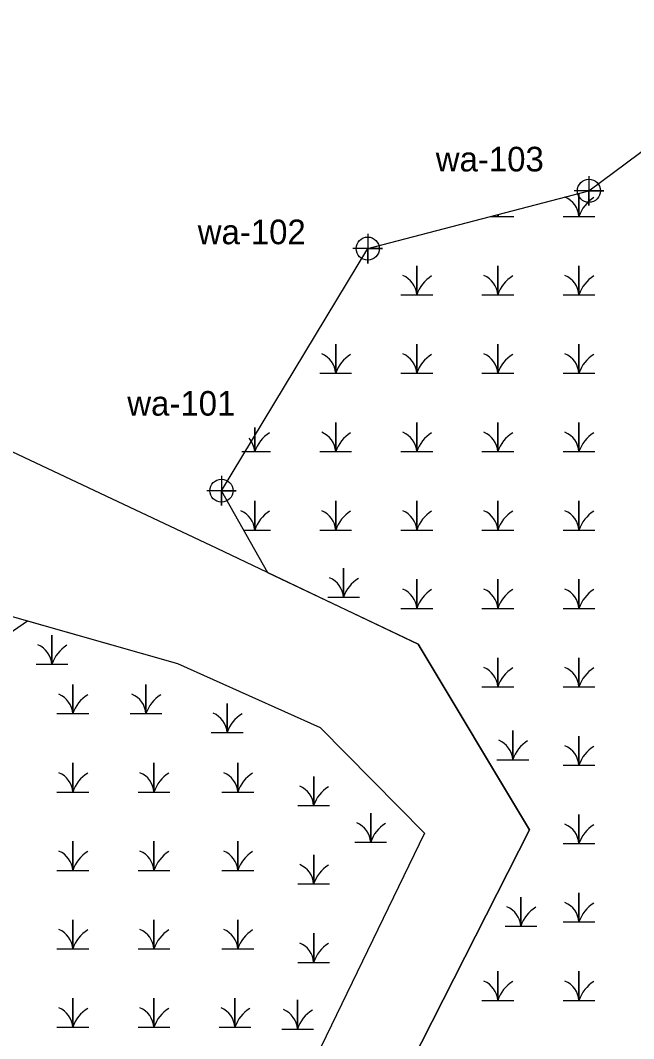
# Model space of a CAD drawing. Extents: x 2379288 to 2381905, y 330670 to 333511.
# Drawn here: x 2380359.8 to 2380484.3, y 332166.7 to 332373.5 of the extents above; entities that cross this region are included whole.
import ezdxf

# ---------------------------------------------------------------- set-up
doc = ezdxf.new("R2010")
doc.units = 0
for name, color, linetype in [('Exist Environmental Wetland Boundary', 7, 'Continuous'), ('Exist Environmental Wetland Boundary Cogo Number', 7, 'Continuous'), ('Exist Environmental Wetland Boundary Cogo Point CELL', 7, 'Continuous'), ('Exist Hydro Jurisdictional Stream or Body of Water Mitigable', 7, 'Continuous'), ('Exist Hydro Swamp or Marsh', 7, 'Continuous')]:
    doc.layers.add(name, color=color, linetype=linetype)

msp = doc.modelspace()

# ---------------------------------------------------------------- linework, layer by layer
at = {"layer": 'Exist Environmental Wetland Boundary'}
for points in [[(2380442.38, 332045.91), (2380445.79, 332068.31), (2380430.27, 332144.34), (2380463.17, 332209.13), (2380440.55, 332246.83), (2380410.07, 332261.34), (2380400.64, 332277.99), (2380430.32, 332327.14), (2380475.22, 332338.88), (2380523.99, 332375.18), (2380571.84, 332459.01), (2380602.28, 332487.78), (2380643.42, 332522.54), (2380698.01, 332520.45), (2380758.16, 332538.88), (2380814.95, 332532.8), (2380827.75, 332553.62), (2380815.96, 332612.38), (2380841.18, 332668.4), (2380857.01, 332670.65), (2380837.85, 332627.97), (2380932.82, 332657.69)], [(2380190.43, 331937.74), (2380215.91, 331979.8), (2380228.91, 332002.01), (2380260.36, 332058.66), (2380273.37, 332080.17), (2380301.41, 332125.81), (2380310.82, 332140.92), (2380328.42, 332178.94), (2380338.55, 332196.72), (2380340.11, 332203.44), (2380335.84, 332213), (2380327.12, 332226.26), (2380352.5, 332245.53), (2380361.25, 332251.56), (2380391.69, 332242.92), (2380420.68, 332229.92), (2380441.85, 332208.47), (2380413.47, 332149.9), (2380414.24, 332071.02), (2380410.1, 331991.07)]]:
    msp.add_lwpolyline(points, dxfattribs=at)
at = {"layer": 'Exist Environmental Wetland Boundary Cogo Point CELL'}
for points in [[(2380475.21, 332341.88), (2380475.21, 332335.88), (2380475.21, 332338.88), (2380478.21, 332338.88), (2380472.21, 332338.88)], [(2380430.32, 332330.14), (2380430.32, 332324.14), (2380430.32, 332327.14), (2380433.32, 332327.14), (2380427.32, 332327.14)], [(2380400.64, 332280.99), (2380400.64, 332274.99), (2380400.64, 332277.99), (2380403.64, 332277.99), (2380397.64, 332277.99)]]:
    msp.add_lwpolyline(points, dxfattribs=at)
for centre in [(2380475.21, 332338.88), (2380430.32, 332327.14), (2380400.64, 332277.99)]:
    msp.add_circle(centre, 2.34, dxfattribs=at)
at = {"layer": 'Exist Hydro Jurisdictional Stream or Body of Water Mitigable'}
for points in [[(2380185.2, 332357.15), (2380244.82, 332322.56), (2380311.82, 332307.72), (2380399.67, 332266.29), (2380440.55, 332246.83), (2380463.17, 332209.13), (2380430.27, 332144.34), (2380445.79, 332068.31), (2380442.38, 332045.91)], [(2380184.84, 332330.77), (2380227.89, 332300.41), (2380296.91, 332269.82), (2380391.69, 332242.92), (2380420.68, 332229.92), (2380441.85, 332208.47), (2380413.47, 332149.9), (2380414.24, 332071.02), (2380410.1, 331991.07)]]:
    msp.add_lwpolyline(points, dxfattribs=at)
at = {"layer": 'Exist Hydro Swamp or Marsh'}
for points in [[(2380469.96, 332333.67), (2380473.19, 332333.67), (2380473.19, 332338.35)], [(2380473.19, 332338.35), (2380473.19, 332333.67), (2380476.42, 332333.67)], [(2380455.29, 332333.67), (2380456.74, 332333.67), (2380456.74, 332334.05)], [(2380456.74, 332334.05), (2380456.74, 332333.67), (2380459.96, 332333.67)], [(2380437.06, 332317.75), (2380440.29, 332317.75), (2380440.29, 332323.67), (2380440.29, 332317.75), (2380443.51, 332317.75)], [(2380453.51, 332317.75), (2380456.74, 332317.75), (2380456.74, 332323.67), (2380456.74, 332317.75), (2380459.96, 332317.75)], [(2380469.96, 332317.75), (2380473.19, 332317.75), (2380473.19, 332323.67), (2380473.19, 332317.75), (2380476.42, 332317.75)], [(2380420.61, 332301.83), (2380423.84, 332301.83), (2380423.84, 332307.75), (2380423.84, 332301.83), (2380427.06, 332301.83)], [(2380437.06, 332301.83), (2380440.29, 332301.83), (2380440.29, 332307.75), (2380440.29, 332301.83), (2380443.51, 332301.83)], [(2380453.51, 332301.83), (2380456.74, 332301.83), (2380456.74, 332307.75), (2380456.74, 332301.83), (2380459.96, 332301.83)], [(2380469.96, 332301.83), (2380473.19, 332301.83), (2380473.19, 332307.75), (2380473.19, 332301.83), (2380476.42, 332301.83)], [(2380420.61, 332285.91), (2380423.84, 332285.91), (2380423.84, 332291.83), (2380423.84, 332285.91), (2380427.06, 332285.91)], [(2380437.06, 332285.91), (2380440.29, 332285.91), (2380440.29, 332291.83), (2380440.29, 332285.91), (2380443.51, 332285.91)], [(2380453.51, 332285.91), (2380456.74, 332285.91), (2380456.74, 332291.83), (2380456.74, 332285.91), (2380459.96, 332285.91)], [(2380469.96, 332285.91), (2380473.19, 332285.91), (2380473.19, 332291.83), (2380473.19, 332285.91), (2380476.42, 332285.91)], [(2380404.8, 332285.91), (2380407.38, 332285.91), (2380407.38, 332290.84)], [(2380407.38, 332290.84), (2380407.38, 332285.91), (2380410.61, 332285.91)], [(2380405.17, 332270), (2380407.38, 332270), (2380407.38, 332275.91), (2380407.38, 332270), (2380410.61, 332270)], [(2380420.61, 332270), (2380423.84, 332270), (2380423.84, 332275.91), (2380423.84, 332270), (2380427.06, 332270)], [(2380437.06, 332270), (2380440.29, 332270), (2380440.29, 332275.91), (2380440.29, 332270), (2380443.51, 332270)], [(2380453.51, 332270), (2380456.74, 332270), (2380456.74, 332275.91), (2380456.74, 332270), (2380459.96, 332270)], [(2380469.96, 332270), (2380473.19, 332270), (2380473.19, 332275.91), (2380473.19, 332270), (2380476.42, 332270)], [(2380422.2, 332256.35), (2380425.42, 332256.35), (2380425.42, 332262.27), (2380425.42, 332256.35), (2380428.65, 332256.35)], [(2380437.06, 332254.08), (2380440.29, 332254.08), (2380440.29, 332260), (2380440.29, 332254.08), (2380443.51, 332254.08)], [(2380453.51, 332254.08), (2380456.74, 332254.08), (2380456.74, 332260), (2380456.74, 332254.08), (2380459.96, 332254.08)], [(2380469.96, 332254.08), (2380473.19, 332254.08), (2380473.19, 332260), (2380473.19, 332254.08), (2380476.42, 332254.08)], [(2380363, 332242.75), (2380366.22, 332242.75), (2380366.22, 332248.67), (2380366.22, 332242.75), (2380369.45, 332242.75)], [(2380453.51, 332238.16), (2380456.74, 332238.16), (2380456.74, 332244.08), (2380456.74, 332238.16), (2380459.96, 332238.16)], [(2380469.96, 332238.16), (2380473.19, 332238.16), (2380473.19, 332244.08), (2380473.19, 332238.16), (2380476.42, 332238.16)], [(2380367.25, 332232.72), (2380370.48, 332232.72), (2380370.48, 332238.64), (2380370.48, 332232.72), (2380373.7, 332232.72)], [(2380382.09, 332232.72), (2380385.31, 332232.72), (2380385.31, 332238.64), (2380385.31, 332232.72), (2380388.54, 332232.72)], [(2380398.57, 332228.87), (2380401.8, 332228.87), (2380401.8, 332234.79), (2380401.8, 332228.87), (2380405.02, 332228.87)], [(2380456.54, 332223.37), (2380459.77, 332223.37), (2380459.77, 332229.29), (2380459.77, 332223.37), (2380462.99, 332223.37)], [(2380469.96, 332222.24), (2380473.19, 332222.24), (2380473.19, 332228.16), (2380473.19, 332222.24), (2380476.42, 332222.24)], [(2380367.25, 332216.8), (2380370.48, 332216.8), (2380370.48, 332222.72), (2380370.48, 332216.8), (2380373.7, 332216.8)], [(2380383.7, 332216.8), (2380386.93, 332216.8), (2380386.93, 332222.72), (2380386.93, 332216.8), (2380390.15, 332216.8)], [(2380400.74, 332216.8), (2380403.96, 332216.8), (2380403.96, 332222.72), (2380403.96, 332216.8), (2380407.19, 332216.8)], [(2380416.12, 332214.05), (2380419.35, 332214.05), (2380419.35, 332219.97), (2380419.35, 332214.05), (2380422.57, 332214.05)], [(2380427.69, 332206.61), (2380430.92, 332206.61), (2380430.92, 332212.52), (2380430.92, 332206.61), (2380434.14, 332206.61)], [(2380469.96, 332206.33), (2380473.19, 332206.33), (2380473.19, 332212.24), (2380473.19, 332206.33), (2380476.42, 332206.33)], [(2380367.25, 332200.88), (2380370.48, 332200.88), (2380370.48, 332206.8), (2380370.48, 332200.88), (2380373.7, 332200.88)], [(2380383.7, 332200.88), (2380386.93, 332200.88), (2380386.93, 332206.8), (2380386.93, 332200.88), (2380390.15, 332200.88)], [(2380400.74, 332200.88), (2380403.96, 332200.88), (2380403.96, 332206.8), (2380403.96, 332200.88), (2380407.19, 332200.88)], [(2380416.12, 332198.13), (2380419.35, 332198.13), (2380419.35, 332204.05), (2380419.35, 332198.13), (2380422.57, 332198.13)], [(2380458.19, 332189.57), (2380461.41, 332189.57), (2380461.41, 332195.48), (2380461.41, 332189.57), (2380464.64, 332189.57)], [(2380469.96, 332190.41), (2380473.19, 332190.41), (2380473.19, 332196.33), (2380473.19, 332190.41), (2380476.42, 332190.41)], [(2380367.25, 332184.96), (2380370.48, 332184.96), (2380370.48, 332190.88), (2380370.48, 332184.96), (2380373.7, 332184.96)], [(2380383.7, 332184.96), (2380386.93, 332184.96), (2380386.93, 332190.88), (2380386.93, 332184.96), (2380390.15, 332184.96)], [(2380400.74, 332184.96), (2380403.96, 332184.96), (2380403.96, 332190.88), (2380403.96, 332184.96), (2380407.19, 332184.96)], [(2380416.12, 332182.22), (2380419.35, 332182.22), (2380419.35, 332188.13), (2380419.35, 332182.22), (2380422.57, 332182.22)], [(2380453.51, 332174.49), (2380456.74, 332174.49), (2380456.74, 332180.41), (2380456.74, 332174.49), (2380459.96, 332174.49)], [(2380469.96, 332174.49), (2380473.19, 332174.49), (2380473.19, 332180.41), (2380473.19, 332174.49), (2380476.42, 332174.49)], [(2380367.25, 332169.05), (2380370.48, 332169.05), (2380370.48, 332174.96), (2380370.48, 332169.05), (2380373.7, 332169.05)], [(2380383.7, 332169.05), (2380386.93, 332169.05), (2380386.93, 332174.96), (2380386.93, 332169.05), (2380390.15, 332169.05)], [(2380400.15, 332169.05), (2380403.38, 332169.05), (2380403.38, 332174.96), (2380403.38, 332169.05), (2380406.61, 332169.05)], [(2380412.86, 332168.68), (2380416.08, 332168.68), (2380416.08, 332174.6), (2380416.08, 332168.68), (2380419.31, 332168.68)]]:
    msp.add_lwpolyline(points, dxfattribs=at)
for centre, radius, start, end in [((2380468.59, 332333.33), 4.61, 4.1403, 67.535), ((2380480.03, 332331.39), 7.21, 122.1274, 161.6222), ((2380452.14, 332333.33), 4.61, 4.1403, 8.7586), ((2380463.58, 332331.39), 7.21, 158.0603, 161.6222), ((2380435.69, 332317.42), 4.61, 4.1403, 67.535), ((2380447.13, 332315.48), 7.21, 122.1274, 161.6222), ((2380452.14, 332317.42), 4.61, 4.1403, 67.535), ((2380463.58, 332315.48), 7.21, 122.1274, 161.6222), ((2380468.59, 332317.42), 4.61, 4.1403, 67.535), ((2380480.03, 332315.48), 7.21, 122.1274, 161.6222), ((2380419.24, 332301.5), 4.61, 4.1403, 67.535), ((2380430.68, 332299.56), 7.21, 122.1274, 161.6222), ((2380435.69, 332301.5), 4.61, 4.1403, 67.535), ((2380447.13, 332299.56), 7.21, 122.1274, 161.6222), ((2380452.14, 332301.5), 4.61, 4.1403, 67.535), ((2380463.58, 332299.56), 7.21, 122.1274, 161.6222), ((2380468.59, 332301.5), 4.61, 4.1403, 67.535), ((2380480.03, 332299.56), 7.21, 122.1274, 161.6222), ((2380414.23, 332283.64), 7.21, 122.1274, 161.6222), ((2380419.24, 332285.58), 4.61, 4.1403, 67.535), ((2380430.68, 332283.64), 7.21, 122.1274, 161.6222), ((2380435.69, 332285.58), 4.61, 4.1403, 67.535), ((2380447.13, 332283.64), 7.21, 122.1274, 161.6222), ((2380452.14, 332285.58), 4.61, 4.1403, 67.535), ((2380463.58, 332283.64), 7.21, 122.1274, 161.6222), ((2380468.59, 332285.58), 4.61, 4.1403, 67.535), ((2380480.03, 332283.64), 7.21, 122.1274, 161.6222), ((2380402.78, 332285.58), 4.61, 4.1403, 41.6376), ((2380402.78, 332269.66), 4.61, 4.1403, 67.535), ((2380414.23, 332267.72), 7.21, 122.1274, 161.6222), ((2380419.24, 332269.66), 4.61, 4.1403, 67.535), ((2380430.68, 332267.72), 7.21, 122.1274, 161.6222), ((2380435.69, 332269.66), 4.61, 4.1403, 67.535), ((2380447.13, 332267.72), 7.21, 122.1274, 161.6222), ((2380452.14, 332269.66), 4.61, 4.1403, 67.535), ((2380463.58, 332267.72), 7.21, 122.1274, 161.6222), ((2380468.59, 332269.66), 4.61, 4.1403, 67.535), ((2380480.03, 332267.72), 7.21, 122.1274, 161.6222), ((2380420.82, 332256.02), 4.61, 4.1403, 67.535), ((2380432.26, 332254.08), 7.21, 122.1274, 161.6222), ((2380435.69, 332253.75), 4.61, 4.1403, 67.535), ((2380447.13, 332251.81), 7.21, 122.1274, 161.6222), ((2380452.14, 332253.75), 4.61, 4.1403, 67.535), ((2380463.58, 332251.81), 7.21, 122.1274, 161.6222), ((2380468.59, 332253.75), 4.61, 4.1403, 67.535), ((2380480.03, 332251.81), 7.21, 122.1274, 161.6222), ((2380361.62, 332242.42), 4.61, 4.1403, 67.535), ((2380373.07, 332240.48), 7.21, 122.1274, 161.6222), ((2380452.14, 332237.83), 4.61, 4.1403, 67.535), ((2380463.58, 332235.89), 7.21, 122.1274, 161.6222), ((2380468.59, 332237.83), 4.61, 4.1403, 67.535), ((2380480.03, 332235.89), 7.21, 122.1274, 161.6222), ((2380365.88, 332232.38), 4.61, 4.1403, 67.535), ((2380377.32, 332230.44), 7.21, 122.1274, 161.6222), ((2380380.71, 332232.38), 4.61, 4.1403, 67.535), ((2380392.15, 332230.44), 7.21, 122.1274, 161.6222), ((2380397.2, 332228.54), 4.61, 4.1403, 67.535), ((2380408.64, 332226.6), 7.21, 122.1274, 161.6222), ((2380455.17, 332223.04), 4.61, 4.1403, 67.535), ((2380466.61, 332221.1), 7.21, 122.1274, 161.6222), ((2380468.59, 332221.91), 4.61, 4.1403, 67.535), ((2380480.03, 332219.97), 7.21, 122.1274, 161.6222), ((2380365.88, 332216.47), 4.61, 4.1403, 67.535), ((2380377.32, 332214.53), 7.21, 122.1274, 161.6222), ((2380382.33, 332216.47), 4.61, 4.1403, 67.535), ((2380393.77, 332214.53), 7.21, 122.1274, 161.6222), ((2380399.36, 332216.47), 4.61, 4.1403, 67.535), ((2380410.8, 332214.53), 7.21, 122.1274, 161.6222), ((2380414.75, 332213.72), 4.61, 4.1403, 67.535), ((2380426.19, 332211.78), 7.21, 122.1274, 161.6222), ((2380426.32, 332206.27), 4.61, 4.1403, 67.535), ((2380437.76, 332204.33), 7.21, 122.1274, 161.6222), ((2380468.59, 332205.99), 4.61, 4.1403, 67.535), ((2380480.03, 332204.05), 7.21, 122.1274, 161.6222), ((2380365.88, 332200.55), 4.61, 4.1403, 67.535), ((2380377.32, 332198.61), 7.21, 122.1274, 161.6222), ((2380382.33, 332200.55), 4.61, 4.1403, 67.535), ((2380393.77, 332198.61), 7.21, 122.1274, 161.6222), ((2380399.36, 332200.55), 4.61, 4.1403, 67.535), ((2380410.8, 332198.61), 7.21, 122.1274, 161.6222), ((2380414.75, 332197.8), 4.61, 4.1403, 67.535), ((2380426.19, 332195.86), 7.21, 122.1274, 161.6222), ((2380456.81, 332189.23), 4.61, 4.1403, 67.535), ((2380468.25, 332187.29), 7.21, 122.1274, 161.6222), ((2380468.59, 332190.08), 4.61, 4.1403, 67.535), ((2380480.03, 332188.14), 7.21, 122.1274, 161.6222), ((2380365.88, 332184.63), 4.61, 4.1403, 67.535), ((2380377.32, 332182.69), 7.21, 122.1274, 161.6222), ((2380382.33, 332184.63), 4.61, 4.1403, 67.535), ((2380393.77, 332182.69), 7.21, 122.1274, 161.6222), ((2380399.36, 332184.63), 4.61, 4.1403, 67.535), ((2380410.8, 332182.69), 7.21, 122.1274, 161.6222), ((2380414.75, 332181.88), 4.61, 4.1403, 67.535), ((2380426.19, 332179.94), 7.21, 122.1274, 161.6222), ((2380452.14, 332174.16), 4.61, 4.1403, 67.535), ((2380463.58, 332172.22), 7.21, 122.1274, 161.6222), ((2380468.59, 332174.16), 4.61, 4.1403, 67.535), ((2380480.03, 332172.22), 7.21, 122.1274, 161.6222), ((2380365.88, 332168.71), 4.61, 4.1403, 67.535), ((2380377.32, 332166.77), 7.21, 122.1274, 161.6222), ((2380382.33, 332168.71), 4.61, 4.1403, 67.535), ((2380393.77, 332166.77), 7.21, 122.1274, 161.6222), ((2380398.78, 332168.71), 4.61, 4.1403, 67.535), ((2380410.22, 332166.77), 7.21, 122.1274, 161.6222), ((2380411.48, 332168.35), 4.61, 4.1403, 67.535), ((2380422.92, 332166.41), 7.21, 122.1274, 161.6222)]:
    msp.add_arc(centre, radius, start, end, dxfattribs=at)

# ---------------------------------------------------------------- texts
at = {"layer": 'Exist Environmental Wetland Boundary Cogo Number'}
for s, p in [('wa-103', (2380444.13, 332342.81)), ('wa-102', (2380395.82, 332328.03)), ('wa-101', (2380381.52, 332293.22))]:
    msp.add_text(s, height=5, dxfattribs=at).set_placement(p)

doc.saveas('drawing.dxf')
